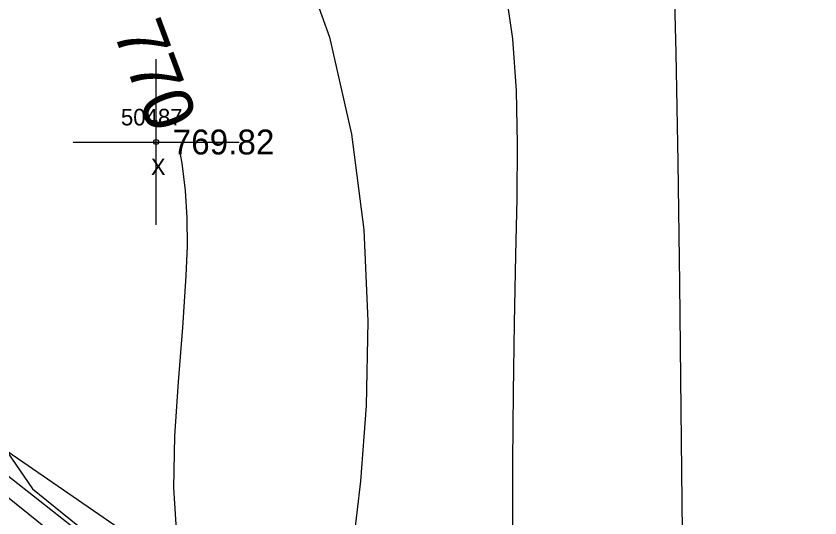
# Model space of a CAD drawing. Extents: x 1378535 to 1380697, y 997729 to 1000024.
# Drawn here: x 1379232.85 to 1379281.31, y 999412.22 to 999442.49 of the extents above; entities that cross this region are included whole.
import ezdxf

# ---------------------------------------------------------------- set-up
doc = ezdxf.new("R2010")
doc.units = 0
for name, color, linetype in [('RD_DTM_BkLn2', 7, 'Continuous'), ('RD_DTM_Major1', 7, 'Continuous'), ('RD_DTM_Major1_Lbl', 7, 'Continuous'), ('RD_DTM_Minor1', 7, 'Continuous'), ('RD_EX_Misc', 7, 'Continuous'), ('RD_EX_Misc_txCode', 7, 'Continuous'), ('RD_EX_TX_Misc_ELEV', 7, 'Continuous'), ('RD_SMD_Locator', 7, 'Continuous')]:
    doc.layers.add(name, color=color, linetype=linetype)

msp = doc.modelspace()

# ---------------------------------------------------------------- linework, layer by layer
at = {"layer": 'RD_DTM_BkLn2'}
msp.add_lwpolyline([(1379494.504, 999194.125), (1379456.694, 999214.003), (1379436.374, 999253.04), (1379388.122, 999297.569), (1379349.799, 999331.884), (1379305.784, 999362.026), (1379275.226, 999386.673), (1379224.721, 999421.459), (1379183.395, 999457.982)], dxfattribs=at)
at = {"layer": 'RD_DTM_Major1'}
msp.add_lwpolyline([(1379242.738, 999434.151), (1379242.844, 999433.629), (1379243.053, 999431.978), (1379243.151, 999430.316), (1379243.158, 999428.611), (1379243.091, 999426.831), (1379242.876, 999423.703), (1379242.615, 999420.432), (1379242.405, 999417.163), (1379242.345, 999414.042), (1379242.533, 999411.213)], dxfattribs=at)
at = {"layer": 'RD_DTM_Minor1'}
for points in [[(1379249.44, 999447.684), (1379251.741, 999441.226), (1379253.077, 999435.378), (1379253.808, 999429.609), (1379254.06, 999424.086), (1379253.954, 999418.976), (1379253.617, 999414.449), (1379253.17, 999410.671)], [(1379272.475, 999445.707), (1379272.624, 999440.274), (1379272.746, 999433.676), (1379272.847, 999426.359), (1379272.93, 999418.77), (1379272.998, 999411.354)], [(1379262.343, 999444.169), (1379262.777, 999441.111), (1379263.001, 999437.99), (1379263.07, 999434.788), (1379263.04, 999431.49), (1379262.967, 999428.077), (1379262.888, 999423.974), (1379262.828, 999419.79), (1379262.789, 999415.621), (1379262.774, 999411.562)], [(1379229.957, 999416.649), (1379232.965, 999414.311), (1379236.272, 999411.681)], [(1379232.326, 999416.221), (1379233.84, 999413.981), (1379236.567, 999411.761)], [(1379230.772, 999414.751), (1379233.59, 999412.484), (1379236.609, 999410.042)]]:
    msp.add_lwpolyline(points, dxfattribs=at)
at = {"layer": 'RD_EX_Misc'}
for p, q in [((1379241.292, 999429.898), (1379241.292, 999439.898)), ((1379236.292, 999434.898), (1379246.292, 999434.898))]:
    msp.add_line(p, q, dxfattribs=at)
at = {"layer": 'RD_SMD_Locator'}
msp.add_circle((1379241.292, 999434.898), 0.15, dxfattribs=at)

# ---------------------------------------------------------------- texts
at = {"layer": 'RD_DTM_Major1_Lbl'}
msp.add_text('770', height=3, rotation=290.4158, dxfattribs=at).set_placement((1379238.68, 999441.58))
at = {"layer": 'RD_EX_Misc_txCode'}
for s, p in [('50487', (1379239.174, 999435.898)), ('X', (1379240.977, 999432.898))]:
    msp.add_text(s, height=1, dxfattribs=at).set_placement(p)
at = {"layer": 'RD_EX_TX_Misc_ELEV'}
msp.add_text('769.82', height=1.5, dxfattribs=at).set_placement((1379242.292, 999434.148))

doc.saveas('drawing.dxf')
